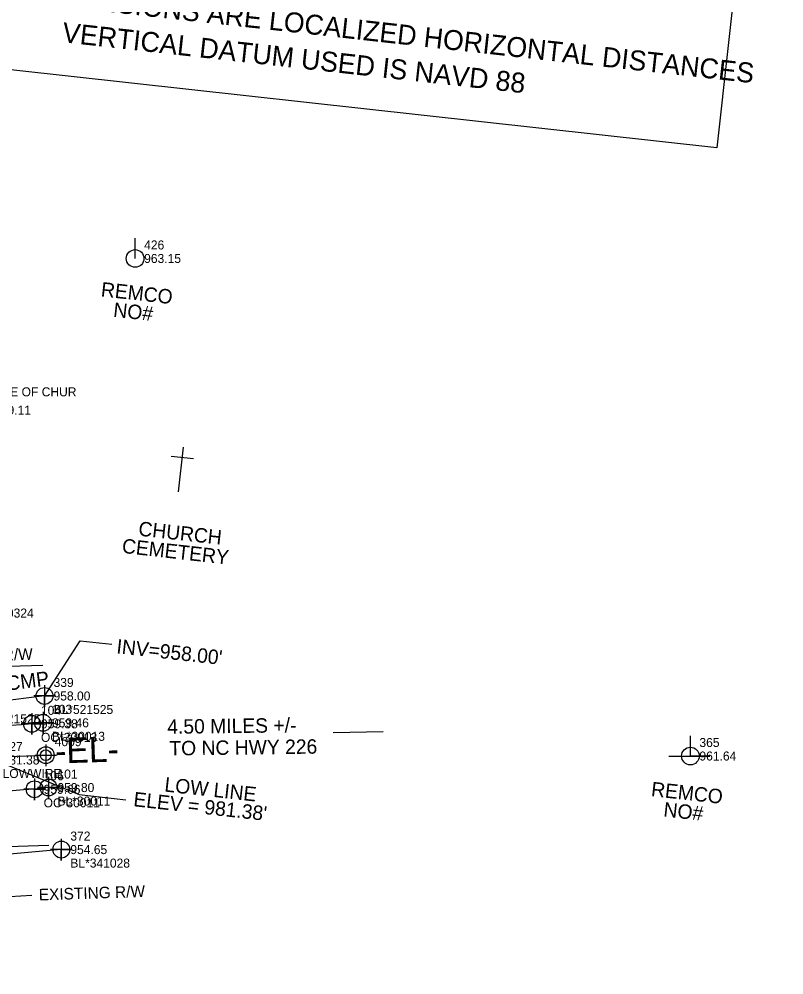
# Model space of a CAD drawing. Extents: x 1150279 to 1151282, y 655434 to 657999.
# Drawn here: x 1151052.7 to 1151264.8, y 657007.4 to 657272.6 of the extents above; entities that cross this region are included whole.
import ezdxf

# ---------------------------------------------------------------- set-up
doc = ezdxf.new("R2010")
doc.units = 0
for name, color, linetype in [('COGO Default Chain', 7, 'Continuous'), ('Cogo Default Point CELL', 7, 'Continuous'), ('COGO Default Point Number', 7, 'Continuous'), ('CTL Bench Mark Cogo Comment', 7, 'Continuous'), ('CTL Sheet Datum Description CELL', 7, 'Continuous'), ('Default Symbol Cogo Comment', 7, 'Continuous'), ('Default Symbol Cogo Elevation', 7, 'Continuous'), ('Default Symbol Cogo Number', 7, 'Continuous'), ('Exist Building Cogo Elevation', 7, 'Continuous'), ('Exist Building Text', 7, 'Continuous'), ('Exist Horizontal Alignment', 7, 'Continuous'), ('Exist Horizontal Alignment Direction Label', 7, 'Continuous'), ('Exist Horizontal Alignment Station Label', 7, 'Continuous'), ('Exist Other Culture Church or Cemetery CELL', 7, 'Continuous'), ('Exist Other Culture Fence Line', 7, 'Continuous'), ('Exist Other Culture Fence Line Cogo Comment', 7, 'Continuous'), ('Exist Other Culture Fence Line Cogo Elevation', 7, 'Continuous'), ('Exist Other Culture Fence Line Cogo Number', 7, 'Continuous'), ('Exist Other Culture Fence Line Cogo Point CELL', 7, 'Continuous'), ('Exist Right of Way Line', 7, 'Continuous'), ('Exist Right of Way Line Leader', 7, 'Continuous'), ('Exist Right of Way Line Text', 7, 'Continuous'), ('Exist Roads EOP', 7, 'Continuous'), ('Exist Roads EOP Cogo Comment', 7, 'Continuous'), ('Exist Roads EOP Cogo Elevation', 7, 'Continuous'), ('Exist Roads EOP Cogo Number', 7, 'Continuous'), ('Exist Roads EOP Cogo Point CELL', 7, 'Continuous'), ('Exist Roads EOP Leader', 7, 'Continuous'), ('Exist Roads EOP Other Cogo Comment', 7, 'Continuous'), ('Exist Roads EOP Text', 7, 'Continuous'), ('Exist Structure Minor Pipes CMP 15 Inch', 7, 'Continuous'), ('Exist Structure Minor Pipes CMP 15 Inch Cogo Comment', 7, 'Continuous'), ('Exist Structure Minor Pipes CMP 15 Inch Cogo Elevation', 7, 'Continuous'), ('Exist Structure Minor Pipes CMP 15 Inch Cogo Number', 7, 'Continuous'), ('Exist Structure Minor Pipes CMP 15 Inch Cogo Point CELL', 7, 'Continuous'), ('Exist Structure Minor Pipes CMP 15 Inch Leader', 7, 'Continuous'), ('Exist Structure Minor Pipes CMP 15 Inch Text', 7, 'Continuous'), ('Exist Utilities Other Located Object Leader', 7, 'Continuous'), ('Exist Utilities Other Located Object Text', 7, 'Continuous'), ('Exist Utilities Power Joint Use Telephone CELL', 7, 'Continuous'), ('Exist Utilities Power Joint Use Telephone Cogo Elevation', 7, 'Continuous'), ('Exist Utilities Power Joint Use Telephone Cogo Number', 7, 'Continuous'), ('Exist Utilities Power Joint Use Telephone Text', 7, 'Continuous'), ('Exist Utilities Power Pole CELL', 7, 'Continuous'), ('Exist Utilities Power Pole Cogo Elevation', 7, 'Continuous'), ('Exist Utilities Power Pole Cogo Number', 7, 'Continuous'), ('Exist Utilities Power Pole Text', 7, 'Continuous')]:
    doc.layers.add(name, color=color, linetype=linetype)

msp = doc.modelspace()

# ---------------------------------------------------------------- linework, layer by layer
at = {"layer": 'COGO Default Chain'}
msp.add_line((1151020.37, 657067.07), (1151060.05, 657068.39), dxfattribs=at)
at = {"layer": 'Cogo Default Point CELL'}
for points in [[(1151060.05, 657071.39), (1151060.05, 657068.39)], [(1151057.05, 657068.39), (1151060.05, 657068.39)], [(1151060.05, 657068.39), (1151063.05, 657068.39)], [(1151060.05, 657068.39), (1151060.05, 657065.39)]]:
    msp.add_lwpolyline(points, dxfattribs=at)
msp.add_circle((1151060.05, 657068.39), 2.34, dxfattribs=at)
at = {"layer": 'CTL Sheet Datum Description CELL'}
msp.add_lwpolyline([(1151001.71, 657263.95), (1151020.3, 657431.92), (1151264.81, 657404.87), (1151246.22, 657236.9)], close=True, dxfattribs=at)
at = {"layer": 'Exist Horizontal Alignment'}
msp.add_line((1151020.37, 657067.07), (1151060.05, 657068.39), dxfattribs=at)
at = {"layer": 'Exist Horizontal Alignment Station Label'}
msp.add_circle((1151060.05, 657068.39), 1.5, dxfattribs=at)
at = {"layer": 'Exist Other Culture Church or Cemetery CELL'}
for p, q in [((1151096.89, 657141.44), (1151098.26, 657153.83)), ((1151094.83, 657151.4), (1151101.08, 657150.7)), ((1151097.58, 657147.66), (1151097.58, 657147.66))]:
    msp.add_line(p, q, dxfattribs=at)
at = {"layer": 'Exist Other Culture Fence Line'}
msp.add_lwpolyline([(1151064.38, 657042.2), (1151035.79, 657039.66), (1150986.53, 657050.15), (1150941.42, 657063.2), (1150898.39, 657078.65), (1150854.86, 657094.99), (1150825.03, 657100.53), (1150812.46, 657091.59), (1150835.17, 657043.74), (1150852.72, 657007.43)], dxfattribs=at)
at = {"layer": 'Exist Other Culture Fence Line Cogo Point CELL'}
msp.add_lwpolyline([(1151064.38, 657045.2), (1151064.38, 657039.2), (1151064.38, 657042.2), (1151067.38, 657042.2), (1151061.38, 657042.2)], dxfattribs=at)
msp.add_circle((1151064.38, 657042.2), 2.34, dxfattribs=at)
at = {"layer": 'Exist Right of Way Line'}
for p, q in [((1151019.53, 657092.05), (1151059.22, 657093.38)), ((1151021.2, 657042.08), (1151060.89, 657043.41))]:
    msp.add_line(p, q, dxfattribs=at)
at = {"layer": 'Exist Right of Way Line Leader'}
msp.add_lwpolyline([(1151041.84, 657042.77), (1151046.96, 657028.97), (1151056.17, 657029.54)], dxfattribs=at)
at = {"layer": 'Exist Roads EOP'}
for p, q in [((1151059.3, 657077.38), (1151056.23, 657077.09)), ((1151060.81, 657059.41), (1151056.97, 657058.93))]:
    msp.add_line(p, q, dxfattribs=at)
for points in [[(1151056.23, 657077.09), (1151010.25, 657076.05), (1150965.32, 657087.79), (1150920.52, 657109.03), (1150919.16, 657109.82)], [(1151056.97, 657058.93), (1151008.05, 657058.3), (1150957.78, 657070.1), (1150911.09, 657090.11), (1150910.09, 657090.54)]]:
    msp.add_spline(points, degree=3, dxfattribs=at)
at = {"layer": 'Exist Roads EOP Cogo Point CELL'}
for points in [[(1151056.23, 657080.09), (1151056.23, 657074.09), (1151056.23, 657077.09), (1151059.23, 657077.09), (1151053.23, 657077.09)], [(1151059.3, 657080.38), (1151059.3, 657074.38), (1151059.3, 657077.38), (1151062.3, 657077.38), (1151056.3, 657077.38)], [(1151056.97, 657061.93), (1151056.97, 657055.93), (1151056.97, 657058.93), (1151059.97, 657058.93), (1151053.97, 657058.93)], [(1151060.81, 657062.41), (1151060.81, 657056.41), (1151060.81, 657059.41), (1151063.81, 657059.41), (1151057.81, 657059.41)]]:
    msp.add_lwpolyline(points, dxfattribs=at)
for centre in [(1151056.23, 657077.09), (1151059.3, 657077.38), (1151056.97, 657058.93), (1151060.81, 657059.41)]:
    msp.add_circle(centre, 2.34, dxfattribs=at)
at = {"layer": 'Exist Roads EOP Leader'}
msp.add_line((1151153.65, 657074.87), (1151139.74, 657074.63), dxfattribs=at)
at = {"layer": 'Exist Structure Minor Pipes CMP 15 Inch'}
msp.add_line((1151059.72, 657084.82), (1151039.52, 657082.26), dxfattribs=at)
at = {"layer": 'Exist Structure Minor Pipes CMP 15 Inch Cogo Point CELL'}
msp.add_lwpolyline([(1151059.72, 657087.82), (1151059.72, 657081.82), (1151059.72, 657084.82), (1151062.72, 657084.82), (1151056.72, 657084.82)], dxfattribs=at)
msp.add_circle((1151059.72, 657084.82), 2.34, dxfattribs=at)
at = {"layer": 'Exist Structure Minor Pipes CMP 15 Inch Leader'}
msp.add_lwpolyline([(1151059.75, 657084.81), (1151069.59, 657100.15), (1151078.38, 657099.18)], dxfattribs=at)
at = {"layer": 'Exist Utilities Other Located Object Leader'}
msp.add_lwpolyline([(1151047.69, 657066.38), (1151069.32, 657057.45), (1151082.27, 657056.02)], dxfattribs=at)
at = {"layer": 'Exist Utilities Power Joint Use Telephone CELL'}
msp.add_line((1151238.88, 657068.16), (1151238.88, 657068.16), dxfattribs=at)
msp.add_lwpolyline([(1151232.94, 657068.16), (1151244.28, 657068.12), (1151238.88, 657068.14), (1151238.88, 657073.78)], dxfattribs=at)
msp.add_circle((1151238.88, 657068.16), 2.45, dxfattribs=at)
at = {"layer": 'Exist Utilities Power Pole CELL'}
for q in [(1151084.85, 657211.84), (1151084.85, 657206.22)]:
    msp.add_line((1151084.85, 657206.22), q, dxfattribs=at)
msp.add_circle((1151084.85, 657206.22), 2.45, dxfattribs=at)

# ---------------------------------------------------------------- texts
at = {"layer": 'COGO Default Point Number'}
msp.add_text('4009', height=2.5, dxfattribs=at).set_placement((1151062.55, 657070.89))
at = {"layer": 'CTL Bench Mark Cogo Comment'}
msp.add_text('ETCH IN SW CORNER OF BRICK & CONCRETE BASE OF CHUR', height=2.5, dxfattribs=at).set_placement((1150967.92, 657167.96))
at = {"layer": 'CTL Sheet Datum Description CELL'}
for s, p in [('ALL LINEAR DIMENSIONS ARE LOCALIZED HORIZONTAL DISTANCES', (1151012.19, 657281.85)), ('VERTICAL DATUM USED IS NAVD 88', (1151064.42, 657266.26))]:
    msp.add_text(s, height=5.535, rotation=353.6867, dxfattribs=at).set_placement(p)
at = {"layer": 'Default Symbol Cogo Comment'}
msp.add_text('LOWWIRE', height=2.5, dxfattribs=at).set_placement((1151048.09, 657062.06))
at = {"layer": 'Default Symbol Cogo Elevation'}
msp.add_text('981.38', height=2.5, dxfattribs=at).set_placement((1151048.09, 657065.81))
at = {"layer": 'Default Symbol Cogo Number'}
msp.add_text('427', height=2.5, dxfattribs=at).set_placement((1151048.09, 657069.56))
at = {"layer": 'Exist Building Cogo Elevation'}
msp.add_text('959.11', height=2.5, dxfattribs=at).set_placement((1151045.74, 657162.89))
at = {"layer": 'Exist Building Text'}
for s, p in [('CHURCH', (1151085.61, 657129.33)), ('CEMETERY', (1151081.06, 657124.55))]:
    msp.add_text(s, height=4, rotation=353.6867, dxfattribs=at).set_placement(p)
at = {"layer": 'Exist Horizontal Alignment Direction Label'}
msp.add_text('-EL-', height=7, rotation=1.9187, dxfattribs=at).set_placement((1151062.75, 657066.07))
at = {"layer": 'Exist Other Culture Fence Line Cogo Comment'}
msp.add_text('BL*341028', height=2.5, dxfattribs=at).set_placement((1151066.88, 657037.2))
at = {"layer": 'Exist Other Culture Fence Line Cogo Elevation'}
msp.add_text('954.65', height=2.5, dxfattribs=at).set_placement((1151066.88, 657040.95))
at = {"layer": 'Exist Other Culture Fence Line Cogo Number'}
msp.add_text('372', height=2.5, dxfattribs=at).set_placement((1151066.88, 657044.7))
at = {"layer": 'Exist Right of Way Line Text'}
for p in [(1151027.03, 657093.9), (1151058.17, 657028.08)]:
    msp.add_text('EXISTING R/W', height=3.2, rotation=1.9187, dxfattribs=at).set_placement(p)
at = {"layer": 'Exist Roads EOP Cogo Comment'}
for s, p in [('OC*30013', (1151058.73, 657072.09)), ('BL*30013', (1151061.8, 657072.38)), ('OC*30011', (1151059.47, 657053.93)), ('BL*30011', (1151063.31, 657054.41))]:
    msp.add_text(s, height=2.5, dxfattribs=at).set_placement(p)
at = {"layer": 'Exist Roads EOP Cogo Elevation'}
for s, p in [('959.38', (1151058.73, 657075.84)), ('959.46', (1151061.8, 657076.13)), ('959.80', (1151063.31, 657058.16)), ('959.66', (1151059.47, 657057.68))]:
    msp.add_text(s, height=2.5, dxfattribs=at).set_placement(p)
at = {"layer": 'Exist Roads EOP Cogo Number'}
for s, p in [('104', (1151058.73, 657079.59)), ('103', (1151061.8, 657079.88)), ('106', (1151059.47, 657061.43)), ('101', (1151063.31, 657061.91))]:
    msp.add_text(s, height=2.5, dxfattribs=at).set_placement(p)
at = {"layer": 'Exist Roads EOP Other Cogo Comment'}
msp.add_text('BL*300324', height=2.5, dxfattribs=at).set_placement((1151040.18, 657106.58))
at = {"layer": 'Exist Roads EOP Text'}
for s, p in [('4.50 MILES +/-', (1151093.79, 657074.3)), ('TO NC HWY 226', (1151094.38, 657068.3))]:
    msp.add_text(s, height=4, rotation=0.7343, dxfattribs=at).set_placement(p)
at = {"layer": 'Exist Structure Minor Pipes CMP 15 Inch Cogo Comment'}
for s, p in [('BL*521525', (1151062.22, 657079.82)), ('EL*521525', (1151042.02, 657077.26))]:
    msp.add_text(s, height=2.5, dxfattribs=at).set_placement(p)
at = {"layer": 'Exist Structure Minor Pipes CMP 15 Inch Cogo Elevation'}
msp.add_text('958.00', height=2.5, dxfattribs=at).set_placement((1151062.22, 657083.57))
at = {"layer": 'Exist Structure Minor Pipes CMP 15 Inch Cogo Number'}
msp.add_text('339', height=2.5, dxfattribs=at).set_placement((1151062.22, 657087.32))
at = {"layer": 'Exist Structure Minor Pipes CMP 15 Inch Text'}
for s, rotation, p in [("INV=958.00'", 353.6867, (1151079.54, 657096.68)), ('15" CMP', 7.2171, (1151040.13, 657085.11))]:
    msp.add_text(s, height=4, rotation=rotation, dxfattribs=at).set_placement(p)
at = {"layer": 'Exist Utilities Other Located Object Text'}
for s, p in [('LOW LINE', (1151092.85, 657058.33)), ("ELEV = 981.38'", (1151084.24, 657054.25))]:
    msp.add_text(s, height=4, rotation=353.6867, dxfattribs=at).set_placement(p)
at = {"layer": 'Exist Utilities Power Joint Use Telephone Cogo Elevation'}
msp.add_text('961.64', height=2.5, dxfattribs=at).set_placement((1151241.38, 657066.91))
at = {"layer": 'Exist Utilities Power Joint Use Telephone Cogo Number'}
msp.add_text('365', height=2.5, dxfattribs=at).set_placement((1151241.38, 657070.66))
at = {"layer": 'Exist Utilities Power Joint Use Telephone Text'}
for s, p in [('REMCO', (1151227.84, 657057.06)), ('NO#', (1151231.27, 657051.4))]:
    msp.add_text(s, height=4, rotation=353.6867, dxfattribs=at).set_placement(p)
at = {"layer": 'Exist Utilities Power Pole Cogo Elevation'}
msp.add_text('963.15', height=2.5, dxfattribs=at).set_placement((1151087.35, 657204.97))
at = {"layer": 'Exist Utilities Power Pole Cogo Number'}
msp.add_text('426', height=2.5, dxfattribs=at).set_placement((1151087.35, 657208.72))
at = {"layer": 'Exist Utilities Power Pole Text'}
for s, p in [('REMCO', (1151075.23, 657195.73)), ('NO#', (1151078.66, 657190.07))]:
    msp.add_text(s, height=4, rotation=353.6867, dxfattribs=at).set_placement(p)

doc.saveas('drawing.dxf')
